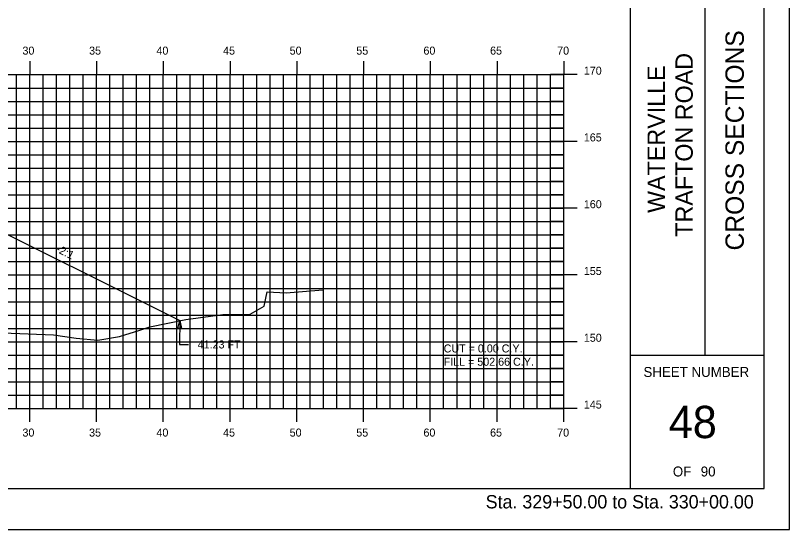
# Model space of a CAD drawing. Extents: x 1141202 to 1141372, y 608981 to 609091.
# Drawn here: x 1141314.4 to 1141372.4, y 608981.3 to 609019.8 of the extents above; entities that cross this region are included whole.
import ezdxf

# ---------------------------------------------------------------- set-up
doc = ezdxf.new("R2010")
doc.units = 0
for name, color, linetype in [('ANNOTATION', 7, 'Continuous'), ('BORDER', 7, 'Continuous'), ('D_Roadway_SlopeLines', 7, 'Continuous'), ('D_Text_Standard', 7, 'Continuous'), ('H_V ANNOTATION', 7, 'Continuous'), ('HIGHWAY_TITLE', 7, 'Continuous'), ('MAJOR', 7, 'Continuous'), ('MINOR', 7, 'Continuous'), ('PLOT BOUNDARY', 7, 'Continuous'), ('S_Roadway_Centerline', 7, 'Continuous')]:
    doc.layers.add(name, color=color, linetype=linetype)

msp = doc.modelspace()

# ---------------------------------------------------------------- linework, layer by layer
msp.add_lwpolyline([(1141247.62, 608998.583), (1141260.596, 609005.071), (1141262.596, 609006.071), (1141267.513, 609008.53), (1141267.514, 609008.53), (1141274.514, 609008.81), (1141285.514, 609009.03), (1141296.514, 609008.81), (1141303.514, 609008.53), (1141308.431, 609006.071), (1141310.431, 609005.071), (1141326.742, 608996.916)])
at = {"layer": 'BORDER'}
for p, q in [((1141360.514, 608984.335), (1141360.514, 609089.335)), ((1141366.105, 608994.338), (1141366.105, 609029.338)), ((1141360.514, 608994.338), (1141370.514, 608994.338))]:
    msp.add_line(p, q, dxfattribs=at)
msp.add_lwpolyline([(1141210.514, 608984.335), (1141370.514, 608984.335), (1141370.514, 609089.335), (1141210.514, 609089.335)], close=True, dxfattribs=at)
at = {"layer": 'D_Roadway_SlopeLines'}
msp.add_lwpolyline([(1141310.431, 609005.071), (1141326.742, 608996.916)], dxfattribs=at)
at = {"layer": 'D_Text_Standard'}
msp.add_lwpolyline([(1141326.742, 608996.916), (1141326.884, 608996.333), (1141326.593, 608996.335)], close=True, dxfattribs=at)
msp.add_lwpolyline([(1141326.742, 608996.916), (1141326.731, 608995.133), (1141327.411, 608995.133)], dxfattribs=at)
at = {"layer": 'MAJOR'}
for p, q in [((1141315.514, 609016.337), (1141315.514, 609015.335)), ((1141320.514, 609016.337), (1141320.514, 609015.335)), ((1141325.514, 609016.337), (1141325.514, 609015.335)), ((1141330.514, 609016.337), (1141330.514, 609015.335)), ((1141335.514, 609016.337), (1141335.514, 609015.335)), ((1141340.514, 609016.337), (1141340.514, 609015.335)), ((1141345.514, 609016.337), (1141345.514, 609015.335)), ((1141350.514, 609016.337), (1141350.514, 609015.335)), ((1141355.514, 609016.337), (1141355.514, 609015.335)), ((1141215.514, 609015.335), (1141355.514, 609015.335)), ((1141215.514, 609015.335), (1141355.514, 609015.335)), ((1141315.514, 608990.335), (1141315.514, 609015.335)), ((1141320.514, 608990.335), (1141320.514, 609015.335)), ((1141325.514, 608990.335), (1141325.514, 609015.335)), ((1141330.514, 608990.335), (1141330.514, 609015.335)), ((1141335.514, 608990.335), (1141335.514, 609015.335)), ((1141340.514, 608990.335), (1141340.514, 609015.335)), ((1141345.514, 608990.335), (1141345.514, 609015.335)), ((1141350.514, 608990.335), (1141350.514, 609015.335)), ((1141356.516, 609015.335), (1141354.512, 609015.335)), ((1141355.514, 608990.335), (1141355.514, 609015.335)), ((1141355.514, 608990.335), (1141355.514, 609015.335)), ((1141215.514, 609010.335), (1141355.514, 609010.335)), ((1141356.516, 609010.335), (1141354.512, 609010.335)), ((1141215.514, 609005.335), (1141355.514, 609005.335)), ((1141356.516, 609005.335), (1141354.512, 609005.335)), ((1141215.514, 609000.335), (1141355.514, 609000.335)), ((1141356.516, 609000.335), (1141354.512, 609000.335)), ((1141215.514, 608995.335), (1141355.514, 608995.335)), ((1141356.516, 608995.335), (1141354.512, 608995.335)), ((1141215.514, 608990.335), (1141355.514, 608990.335)), ((1141215.514, 608990.335), (1141355.514, 608990.335)), ((1141315.514, 608989.333), (1141315.514, 608990.335)), ((1141320.514, 608989.333), (1141320.514, 608990.335)), ((1141325.514, 608989.333), (1141325.514, 608990.335)), ((1141330.514, 608989.333), (1141330.514, 608990.335)), ((1141335.514, 608989.333), (1141335.514, 608990.335)), ((1141340.514, 608989.333), (1141340.514, 608990.335)), ((1141345.514, 608989.333), (1141345.514, 608990.335)), ((1141350.514, 608989.333), (1141350.514, 608990.335)), ((1141356.516, 608990.335), (1141354.512, 608990.335)), ((1141355.514, 608989.333), (1141355.514, 608990.335))]:
    msp.add_line(p, q, dxfattribs=at)
at = {"layer": 'MINOR'}
for p, q in [((1141314.514, 608990.335), (1141314.514, 609015.335)), ((1141316.514, 608990.335), (1141316.514, 609015.335)), ((1141317.514, 608990.335), (1141317.514, 609015.335)), ((1141318.514, 608990.335), (1141318.514, 609015.335)), ((1141319.514, 608990.335), (1141319.514, 609015.335)), ((1141321.514, 608990.335), (1141321.514, 609015.335)), ((1141322.514, 608990.335), (1141322.514, 609015.335)), ((1141323.514, 608990.335), (1141323.514, 609015.335)), ((1141324.514, 608990.335), (1141324.514, 609015.335)), ((1141326.514, 608990.335), (1141326.514, 609015.335)), ((1141327.514, 608990.335), (1141327.514, 609015.335)), ((1141328.514, 608990.335), (1141328.514, 609015.335)), ((1141329.514, 608990.335), (1141329.514, 609015.335)), ((1141331.514, 608990.335), (1141331.514, 609015.335)), ((1141332.514, 608990.335), (1141332.514, 609015.335)), ((1141333.514, 608990.335), (1141333.514, 609015.335)), ((1141334.514, 608990.335), (1141334.514, 609015.335)), ((1141336.514, 608990.335), (1141336.514, 609015.335)), ((1141337.514, 608990.335), (1141337.514, 609015.335)), ((1141338.514, 608990.335), (1141338.514, 609015.335)), ((1141339.514, 608990.335), (1141339.514, 609015.335)), ((1141341.514, 608990.335), (1141341.514, 609015.335)), ((1141342.514, 608990.335), (1141342.514, 609015.335)), ((1141343.514, 608990.335), (1141343.514, 609015.335)), ((1141344.514, 608990.335), (1141344.514, 609015.335)), ((1141346.514, 608990.335), (1141346.514, 609015.335)), ((1141347.514, 608990.335), (1141347.514, 609015.335)), ((1141348.514, 608990.335), (1141348.514, 609015.335)), ((1141349.514, 608990.335), (1141349.514, 609015.335)), ((1141351.514, 608990.335), (1141351.514, 609015.335)), ((1141352.514, 608990.335), (1141352.514, 609015.335)), ((1141353.514, 608990.335), (1141353.514, 609015.335)), ((1141354.514, 608990.335), (1141354.514, 609015.335)), ((1141215.514, 609014.335), (1141355.514, 609014.335)), ((1141355.514, 609014.335), (1141354.512, 609014.335)), ((1141215.514, 609013.335), (1141355.514, 609013.335)), ((1141355.514, 609013.335), (1141354.512, 609013.335)), ((1141215.514, 609012.335), (1141355.514, 609012.335)), ((1141355.514, 609012.335), (1141354.512, 609012.335)), ((1141215.514, 609011.335), (1141355.514, 609011.335)), ((1141355.514, 609011.335), (1141354.512, 609011.335)), ((1141215.514, 609009.335), (1141355.514, 609009.335)), ((1141355.514, 609009.335), (1141354.512, 609009.335)), ((1141215.514, 609008.335), (1141355.514, 609008.335)), ((1141355.514, 609008.335), (1141354.512, 609008.335)), ((1141215.514, 609007.335), (1141355.514, 609007.335)), ((1141355.514, 609007.335), (1141354.512, 609007.335)), ((1141215.514, 609006.335), (1141355.514, 609006.335)), ((1141355.514, 609006.335), (1141354.512, 609006.335)), ((1141215.514, 609004.335), (1141355.514, 609004.335)), ((1141355.514, 609004.335), (1141354.512, 609004.335)), ((1141215.514, 609003.335), (1141355.514, 609003.335)), ((1141355.514, 609003.335), (1141354.512, 609003.335)), ((1141215.514, 609002.335), (1141355.514, 609002.335)), ((1141355.514, 609002.335), (1141354.512, 609002.335)), ((1141215.514, 609001.335), (1141355.514, 609001.335)), ((1141355.514, 609001.335), (1141354.512, 609001.335)), ((1141215.514, 608999.335), (1141355.514, 608999.335)), ((1141355.514, 608999.335), (1141354.512, 608999.335)), ((1141215.514, 608998.335), (1141355.514, 608998.335)), ((1141355.514, 608998.335), (1141354.512, 608998.335)), ((1141215.514, 608997.335), (1141355.514, 608997.335)), ((1141355.514, 608997.335), (1141354.512, 608997.335)), ((1141215.514, 608996.335), (1141355.514, 608996.335)), ((1141355.514, 608996.335), (1141354.512, 608996.335)), ((1141215.514, 608994.335), (1141355.514, 608994.335)), ((1141355.514, 608994.335), (1141354.512, 608994.335)), ((1141215.514, 608993.335), (1141355.514, 608993.335)), ((1141355.514, 608993.335), (1141354.512, 608993.335)), ((1141215.514, 608992.335), (1141355.514, 608992.335)), ((1141355.514, 608992.335), (1141354.512, 608992.335)), ((1141215.514, 608991.335), (1141355.514, 608991.335)), ((1141355.514, 608991.335), (1141354.512, 608991.335))]:
    msp.add_line(p, q, dxfattribs=at)
at = {"layer": 'PLOT BOUNDARY'}
msp.add_lwpolyline([(1141202.421, 608981.276), (1141372.421, 608981.276), (1141372.421, 609091.276), (1141202.421, 609091.276)], close=True, dxfattribs=at)
at = {"layer": 'S_Roadway_Centerline'}
msp.add_lwpolyline([(1141311.573, 608996.071), (1141317.289, 608995.862), (1141318.983, 608995.6), (1141320.608, 608995.46), (1141322.233, 608995.725), (1141323.758, 608996.196), (1141324.505, 608996.449), (1141327.202, 608997.012), (1141329.965, 608997.372), (1141332.031, 608997.405), (1141333.058, 608997.989), (1141333.296, 608999.082), (1141334.71, 608998.999), (1141337.475, 608999.227)], dxfattribs=at)

# ---------------------------------------------------------------- texts
at = {"layer": 'ANNOTATION'}
msp.add_text('-2:1', height=0.6, rotation=333.43495, dxfattribs=at).set_placement((1141317.41, 609002.1))
at = {"layer": 'BORDER'}
msp.add_text('CROSS SECTIONS', height=1.37787, rotation=90, dxfattribs=at).set_placement((1141368.999, 609002.172))
for s, height, p in [('SHEET NUMBER', 0.74527, (1141361.48, 608992.701)), ('48', 2.4194, (1141363.376, 608988.118)), ('OF', 0.7453, (1141363.681, 608985.248)), ('90', 0.7453, (1141365.771, 608985.248))]:
    msp.add_text(s, height=height, dxfattribs=at).set_placement(p)
at = {"layer": 'D_Text_Standard'}
for s, p in [('41.23 FT', (1141328.091, 608994.833)), ('CUT = 0.00 C.Y.', (1141346.514, 608994.535)), ('FILL = 502.66 C.Y.', (1141346.514, 608993.539))]:
    msp.add_text(s, height=0.6, dxfattribs=at).set_placement(p)
at = {"layer": 'H_V ANNOTATION'}
for s, height, p in [('30', 0.6, (1141314.963, 609016.835)), ('35', 0.6, (1141319.955, 609016.835)), ('40', 0.6, (1141325, 609016.835)), ('45', 0.6, (1141329.992, 609016.835)), ('50', 0.6, (1141334.979, 609016.835)), ('55', 0.6, (1141339.971, 609016.835)), ('60', 0.6, (1141345, 609016.835)), ('65', 0.6, (1141349.992, 609016.835)), ('70', 0.6, (1141355.016, 609016.835)), ('170', 0.6, (1141357.014, 609015.335)), ('165', 0.6, (1141357.014, 609010.335)), ('160', 0.6, (1141357.014, 609005.335)), ('155', 0.6, (1141357.014, 609000.335)), ('150', 0.6, (1141357.014, 608995.335)), ('145', 0.6, (1141357.014, 608990.335)), ('30', 0.6, (1141314.963, 608988.235)), ('35', 0.6, (1141319.955, 608988.235)), ('40', 0.6, (1141325, 608988.235)), ('45', 0.6, (1141329.992, 608988.235)), ('50', 0.6, (1141334.979, 608988.235)), ('55', 0.6, (1141339.971, 608988.235)), ('60', 0.6, (1141345, 608988.235)), ('65', 0.6, (1141349.992, 608988.235)), ('70', 0.6, (1141355.016, 608988.235)), ('Sta. 329+50.00 to Sta. 330+00.00', 1.0002, (1141349.66, 608982.855))]:
    msp.add_text(s, height=height, dxfattribs=at).set_placement(p)
at = {"layer": 'HIGHWAY_TITLE'}
for s, height, p in [('TRAFTON ROAD', 1.30428, (1141365.174, 609003.201)), ('WATERVILLE', 1.3043, (1141363.087, 609004.98))]:
    msp.add_text(s, height=height, rotation=90, dxfattribs=at).set_placement(p)

doc.saveas('drawing.dxf')
